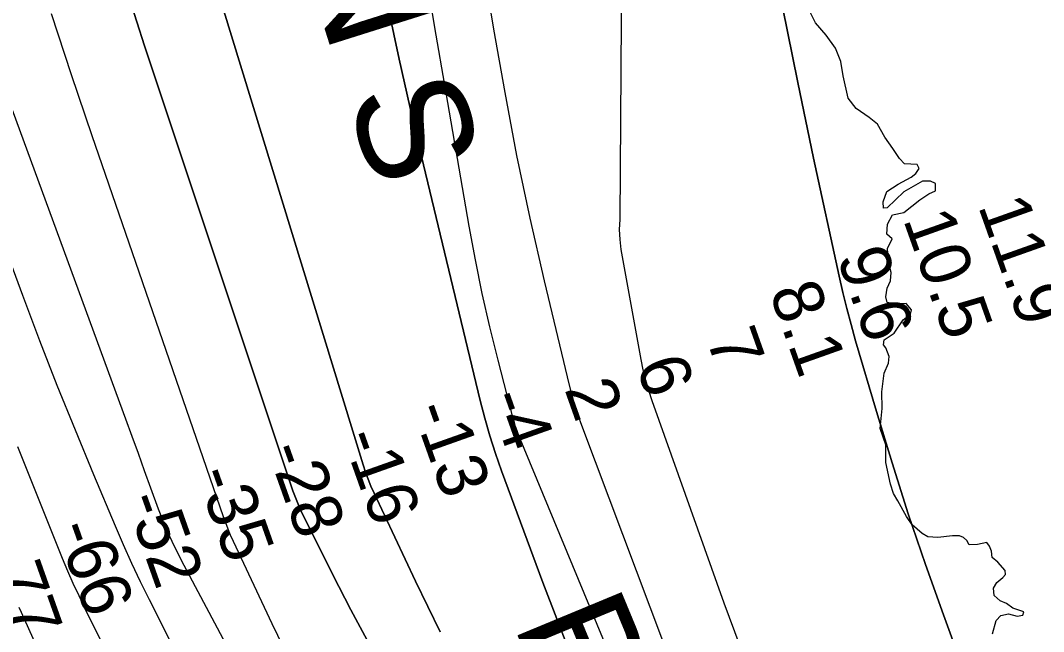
# Model space of a CAD drawing. Extents: x 3187622 to 3225504, y 800805 to 826213.
# Drawn here: x 3198035 to 3199396, y 819837 to 820650 of the extents above; entities that cross this region are included whole.
import ezdxf

# ---------------------------------------------------------------- set-up
doc = ezdxf.new("R2010")
doc.units = 0
for name, color, linetype in [('V-RIVR-EDGE', 7, 'Continuous'), ('V-RIVR-IDEN', 7, 'Continuous'), ('V-RIVR-RANG', 7, 'Continuous'), ('V-TOPO-DPTH', 7, 'Continuous'), ('V-TOPO-MAJR', 7, 'Continuous'), ('V-TOPO-MINR', 7, 'Continuous'), ('V-TOPO-WATR', 7, 'Continuous')]:
    doc.layers.add(name, color=color, linetype=linetype)

msp = doc.modelspace()

# ---------------------------------------------------------------- linework, layer by layer
at = {"layer": 'V-RIVR-EDGE'}
for points in [[(3199194.7, 820359.4), (3199187.7, 820365.5), (3199188.6, 820379), (3199195.2, 820391.2), (3199210, 820394.6), (3199231.3, 820411.5), (3199243.5, 820419.3), (3199252.2, 820423.2), (3199252.2, 820433.2), (3199245.7, 820436.2), (3199234.8, 820436.3), (3199210, 820422), (3199187.8, 820400.7), (3199183, 820400.3), (3199182.6, 820408.6), (3199187.4, 820422.5), (3199202.7, 820432), (3199220.1, 820441.5), (3199226.2, 820446.3), (3199230.5, 820452.8), (3199227.9, 820458.5), (3199211, 820459.4), (3199204.5, 820466.3), (3199195.4, 820479.4), (3199185, 820494.6), (3199175, 820512.1), (3199163.8, 820520.8), (3199146.8, 820533), (3199136, 820546.5), (3199129.6, 820576.1), (3199126.1, 820595.2), (3199119.2, 820613), (3199106.7, 820630.5), (3199092.4, 820646.6), (3199085.4, 820660.9)], [(3199328.1, 819834), (3199332.9, 819851.8), (3199339, 819858.3), (3199349.5, 819860.5), (3199360.8, 819857.4), (3199368.6, 819859.1), (3199369.9, 819863.5), (3199355.2, 819868.3), (3199346.5, 819874.4), (3199338.2, 819877.9), (3199330.4, 819884.9), (3199329.6, 819894.9), (3199333.9, 819902.2), (3199341.8, 819909.2), (3199345.3, 819913.1), (3199344.8, 819918.3), (3199335.3, 819929.2), (3199327.5, 819935.7), (3199326.7, 819944), (3199324.1, 819950.5), (3199320.6, 819955.7), (3199308, 819952.7), (3199297.1, 819952.3), (3199294.1, 819958.4), (3199289.7, 819962.3), (3199284.1, 819964.5), (3199275, 819964.5), (3199255.4, 819962.4), (3199241.9, 819963.3), (3199234.6, 819967.7), (3199221.1, 819979), (3199213.7, 819990.3), (3199202.1, 820010.8), (3199196.4, 820020.8), (3199192.6, 820033), (3199186.1, 820062.1), (3199186.2, 820085.6), (3199178.8, 820107.4), (3199181.5, 820133.9), (3199180.7, 820156), (3199183.8, 820180.8), (3199189.9, 820194.3), (3199190.8, 820203), (3199186, 820214.3), (3199183, 820218.6), (3199183.9, 820225.1), (3199197.4, 820234.2), (3199209.2, 820251.6), (3199219.2, 820259.4), (3199220.5, 820265), (3199213.1, 820273.3), (3199199.2, 820272.5), (3199187.9, 820274.7), (3199186.2, 820282.1), (3199188, 820293.8), (3199192.4, 820303.8), (3199193.3, 820314.7), (3199189.8, 820327.7), (3199188.5, 820346.4), (3199194.7, 820359.4)]]:
    msp.add_lwpolyline(points, dxfattribs=at)
at = {"layer": 'V-TOPO-DPTH'}
for points in [[(3198927.4, 819724.6), (3198781.7, 820111), (3198777, 820124.3), (3198772.6, 820137.8), (3198768.7, 820151.3), (3198765.2, 820165), (3198732.2, 820303.6), (3198713.2, 820386.9), (3198695.5, 820470.3), (3198679.6, 820554.2), (3198664.8, 820638.2), (3198589.7, 821094.6)], [(3198927.4, 819724.6), (3198781.7, 820111), (3198777, 820124.3), (3198772.6, 820137.8), (3198768.7, 820151.3), (3198765.2, 820165), (3198732.2, 820303.6), (3198713.2, 820386.9), (3198695.5, 820470.3), (3198679.6, 820554.2), (3198664.8, 820638.2), (3198589.7, 821094.6)], [(3198209.4, 820976.5), (3198490.7, 820058.9), (3198493.9, 820049.2), (3198497.4, 820039.7), (3198501.2, 820030.4), (3198505.4, 820021.1), (3198560.7, 819904), (3198593.4, 819836.6)], [(3198593.4, 819836.6), (3198560.7, 819904), (3198505.4, 820021.1), (3198501.2, 820030.4), (3198497.4, 820039.7), (3198493.9, 820049.2), (3198490.7, 820058.9), (3198209.4, 820976.5)], [(3198519, 820692.6), (3198538.7, 820598.2), (3198560.1, 820504.1), (3198646.5, 820144.6), (3198652.7, 820120.9), (3198659.4, 820097.4), (3198666.9, 820074.1), (3198675, 820050.9), (3198729.9, 819902.4), (3198767.2, 819805.7), (3198806.3, 819709.8), (3198848.1, 819615), (3198891.7, 819521), (3199035, 819223.7), (3199038.4, 819217), (3199042, 819210.5), (3199045.8, 819204.1), (3199049.9, 819197.8), (3199090.3, 819139), (3199115, 819103.7), (3199140.3, 819068.8), (3199166.3, 819034.4), (3199192.8, 819000.3), (3199485.2, 818632.6)], [(3199485.2, 818632.6), (3199192.8, 819000.3), (3199166.3, 819034.4), (3199140.3, 819068.8), (3199115, 819103.7), (3199090.3, 819139), (3199049.9, 819197.8), (3199045.8, 819204.1), (3199042, 819210.5), (3199038.4, 819217), (3199035, 819223.7), (3198891.7, 819521), (3198848.1, 819615), (3198806.3, 819709.8), (3198767.2, 819805.7), (3198729.9, 819902.4), (3198675, 820050.9), (3198666.9, 820074.1), (3198659.4, 820097.4), (3198652.7, 820120.9), (3198646.5, 820144.6), (3198560.1, 820504.1), (3198538.7, 820598.2), (3198519, 820692.6)], [(3198179.4, 820680.5), (3198200.1, 820616.3), (3198397.5, 820024.4), (3198400.7, 820015.4), (3198404.2, 820006.5), (3198408.1, 819997.8), (3198412.2, 819989.2), (3198450.6, 819912.6), (3198474.5, 819866.1), (3198499.1, 819819.8)], [(3198499.1, 819819.8), (3198474.5, 819866.1), (3198450.6, 819912.6), (3198412.2, 819989.2), (3198408.1, 819997.8), (3198404.2, 820006.5), (3198400.7, 820015.4), (3198397.5, 820024.4), (3198200.1, 820616.3), (3198179.4, 820680.5)], [(3199048.9, 820667.9), (3199069.1, 820567.3), (3199090.1, 820466.9), (3199124.2, 820309.6), (3199129.1, 820288.1), (3199134.3, 820266.6), (3199140, 820245.3), (3199146, 820224), (3199173.7, 820129.8), (3199194.4, 820061.6), (3199216, 819993.8), (3199238.9, 819926.4), (3199262.7, 819859.3), (3199420, 819428.5)], [(3199048.9, 820667.9), (3199069.1, 820567.3), (3199090.1, 820466.9), (3199124.2, 820309.6), (3199129.1, 820288.1), (3199134.3, 820266.6), (3199140, 820245.3), (3199146, 820224), (3199173.7, 820129.8), (3199194.4, 820061.6), (3199216, 819993.8), (3199238.9, 819926.4), (3199262.7, 819859.3), (3199420, 819428.5)]]:
    msp.add_lwpolyline(points, dxfattribs=at)
at = {"layer": 'V-TOPO-MAJR'}
msp.add_lwpolyline([(3198399.8, 819785.2), (3198369.6, 819847.6), (3198318.2, 819957.1), (3198314.6, 819965.2), (3198311.2, 819973.4), (3198308, 819981.6), (3198305, 819989.9), (3198130.3, 820496.4), (3198102.9, 820577.5), (3198076.4, 820658.8)], dxfattribs=at)
at = {"layer": 'V-TOPO-MINR'}
for points in [[(3199408.3, 818932.1), (3199379.2, 818983.9), (3199224.4, 819269.3), (3199218.4, 819280.6), (3199212.6, 819292.1), (3199207.1, 819303.7), (3199201.8, 819315.4), (3199127, 819484.3), (3199085.6, 819580.9), (3199045.5, 819678.1), (3199007.7, 819776.2), (3198971.3, 819874.8), (3198875.3, 820144.1), (3198870.8, 820157.6), (3198866.9, 820171.3), (3198863.5, 820185.1), (3198860.7, 820199.1), (3198834.3, 820345.3), (3198832.7, 820358.6), (3198832, 820372), (3198832.7, 820385.3), (3198837.6, 821114.9)], [(3198927.4, 819724.6), (3198781.7, 820111), (3198777, 820124.3), (3198772.6, 820137.8), (3198768.7, 820151.3), (3198765.2, 820165), (3198732.2, 820303.6), (3198713.2, 820386.9), (3198695.5, 820470.3), (3198679.6, 820554.2), (3198664.8, 820638.2), (3198589.7, 821094.6)], [(3198593.4, 819836.6), (3198560.7, 819904), (3198505.4, 820021.1), (3198501.2, 820030.4), (3198497.4, 820039.7), (3198493.9, 820049.2), (3198490.7, 820058.9), (3198209.4, 820976.5)], [(3199485.2, 818632.6), (3199192.8, 819000.3), (3199166.3, 819034.4), (3199140.3, 819068.8), (3199115, 819103.7), (3199090.3, 819139), (3199049.9, 819197.8), (3199045.8, 819204.1), (3199042, 819210.5), (3199038.4, 819217), (3199035, 819223.7), (3198891.7, 819521), (3198848.1, 819615), (3198806.3, 819709.8), (3198767.2, 819805.7), (3198729.9, 819902.4), (3198675, 820050.9), (3198666.9, 820074.1), (3198659.4, 820097.4), (3198652.7, 820120.9), (3198646.5, 820144.6), (3198560.1, 820504.1), (3198538.7, 820598.2), (3198519, 820692.6)], [(3198849.5, 819732.1), (3198697.7, 820098.9), (3198695.7, 820104.3), (3198693.7, 820109.7), (3198692, 820115.2), (3198690.4, 820120.7), (3198670.5, 820197.9), (3198659.6, 820242.3), (3198649.4, 820286.7), (3198640.3, 820331.5), (3198632, 820376.3), (3198599, 820566.7), (3198588.1, 820630.4), (3198577.2, 820694.2)], [(3198499.1, 819819.8), (3198474.5, 819866.1), (3198450.6, 819912.6), (3198412.2, 819989.2), (3198408.1, 819997.8), (3198404.2, 820006.5), (3198400.7, 820015.4), (3198397.5, 820024.4), (3198200.1, 820616.3), (3198179.4, 820680.5)], [(3198354.2, 819584.6), (3198206.5, 819879.1), (3198194.6, 819903.3), (3198183.1, 819927.8), (3198172, 819952.4), (3198161.3, 819977.2), (3198132.5, 820045.6), (3198108, 820104.8), (3198084, 820164.3), (3198060.8, 820224), (3198038.2, 820284), (3197928.9, 820578.8)], [(3198570.2, 819328.1), (3198249.3, 819931.7), (3198245, 819940), (3198240.8, 819948.3), (3198236.7, 819956.7), (3198232.8, 819965.1), (3198229, 819973.7), (3198225.4, 819982.3), (3198222, 819990.9), (3198218.7, 819999.7), (3198208.4, 820028), (3198200.1, 820050.9), (3198191.8, 820073.8), (3198183.4, 820096.7), (3198175.1, 820119.6), (3198011.3, 820567.1)], [(3198834.6, 818587), (3198599.6, 818972), (3198594.9, 818979.8), (3198590.3, 818987.6), (3198585.8, 818995.5), (3198581.3, 819003.5), (3198392, 819344.2), (3198341.9, 819435.8), (3198292.7, 819527.8), (3198244.7, 819620.6), (3198197.6, 819713.7), (3198120.7, 819868.3), (3198112.9, 819884.6), (3198105.3, 819901), (3198098.1, 819917.6), (3198091.1, 819934.3), (3198031.3, 820082.8)], [(3198878.7, 818300.2), (3198513.8, 818936.3), (3198511.3, 818940.7), (3198508.8, 818945), (3198506.4, 818949.4), (3198504, 818953.8), (3198227.3, 819465.2), (3198191.9, 819532.3), (3198157.5, 819599.9), (3198124.6, 819668.3), (3198092.7, 819737.2), (3198036.3, 819862.3), (3198033.4, 819869)]]:
    msp.add_lwpolyline(points, dxfattribs=at)
at = {"layer": 'V-TOPO-WATR'}
msp.add_lwpolyline([(3199420, 819428.5), (3199262.7, 819859.3), (3199238.9, 819926.4), (3199216, 819993.8), (3199194.4, 820061.6), (3199173.7, 820129.8), (3199146, 820224), (3199140, 820245.3), (3199134.3, 820266.6), (3199129.1, 820288.1), (3199124.2, 820309.6), (3199090.1, 820466.9), (3199069.1, 820567.3), (3199048.9, 820667.9)], dxfattribs=at)

# ---------------------------------------------------------------- texts
at = {"layer": 'V-RIVR-IDEN'}
for s, rotation, p in [('A N S', 287.5204, (3198350.5, 820920.9)), ('B E N D', 292.5256, (3198689.8, 819847.3))]:
    msp.add_text(s, height=150, rotation=rotation, dxfattribs=at).set_placement(p)
at = {"layer": 'V-RIVR-RANG'}
for s, p in [('11.9', (3199308.5, 820403.3)), ('10.5', (3199208.8, 820385.4)), ('9.6', (3199120.6, 820335)), ('8.1', (3199030.7, 820289.2)), ('7', (3198946.7, 820227)), ('6', (3198853.3, 820191)), ('2', (3198758.3, 820159.9)), ('-4', (3198656.2, 820148.4)), ('-13', (3198555.7, 820132.5)), ('-16', (3198462.6, 820096)), ('-28', (3198362.6, 820078.8)), ('-35', (3198267.9, 820046.7)), ('-52', (3198173.8, 820012.6)), ('-66', (3198081.2, 819974.6)), ('-77', (3197986, 819944))]:
    msp.add_text(s, height=67, rotation=289.5507, dxfattribs=at).set_placement(p)

doc.saveas('drawing.dxf')
